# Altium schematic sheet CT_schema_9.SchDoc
size 146 x 119 mm
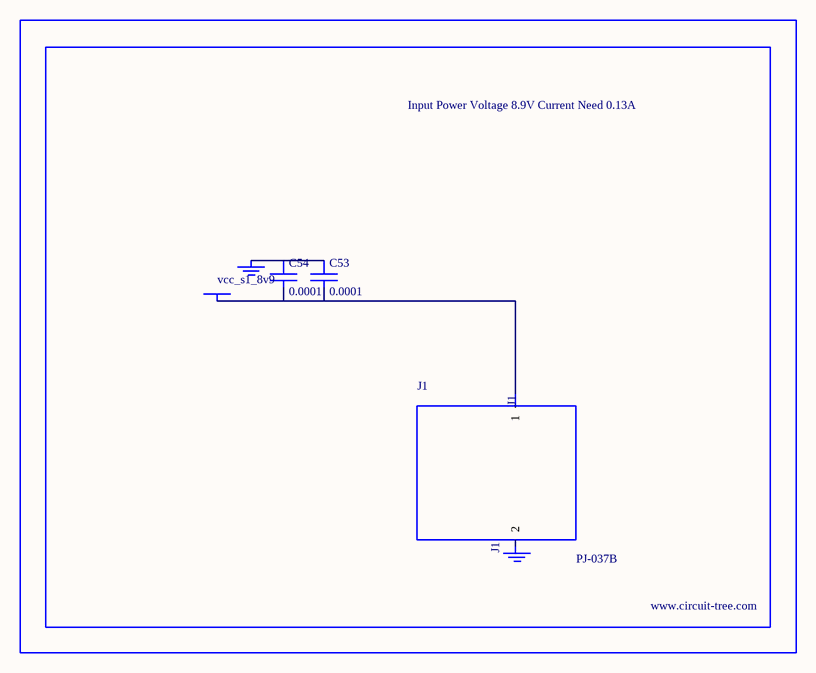
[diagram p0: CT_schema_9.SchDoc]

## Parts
BORDER8  (no value)
C53  0.0001  [EXV-9H]
C54  0.0001  [EXV-9H]
GND_INSTANCE_8_0  (no value)
GND_INSTANCE_8_1  (no value)
J1  PJ-037B  [PJ-037B_PACKAGE]
POWER_INSTANCE_8_0  vcc_s1_8v9

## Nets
NetC53_1: C53.1 C54.1 GND_INSTANCE_8_0.0(GND)
NetC53_2: C53.2 C54.2 J1.1 POWER_INSTANCE_8_0.0(PWR)

Not connected (* = marked no-connect by the designer): GND_INSTANCE_8_1 0(GND); J1 2

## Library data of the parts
BORDER8 = BORDER_PAGE8
C53 C54 = EDK107M035A9HAA
GND_INSTANCE_8_0 GND_INSTANCE_8_1 = GND
POWER_INSTANCE_8_0 = PWR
